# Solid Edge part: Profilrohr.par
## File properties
Username: bmolnar
Dokumentum tartalom típus: 0
Author: bmolnar
Last saved by: bmolnar
Revision: 97
Sűrűség: 0,000 kg/m^3
Pontosság: 0,990
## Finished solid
Body 1: solid body, 175 faces, 519 edges, 346 vertices.
  Faces by surface: cylinder 107, plane 68
  Edges by curve: line 305, circle 214
Bounding box of the edges (mm): 60.200 x 60.200 x 2844.000, from (-30.1, -30.1, -2784.5) to (30.1, 30.1, 59.5).
Cylindrical faces by radius (mm): R0.1 x16, R0.2 x30, R0.5 x28, R1 x8, R3.75 x8, R5 x4, R6 x4, R25 x1, R27 x8
Planar faces by outward normal: +x 6, +y 6, +z 1, -x 4, -y 4, -z 1, oblique 46
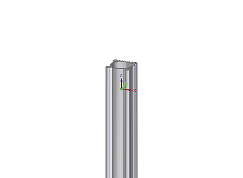
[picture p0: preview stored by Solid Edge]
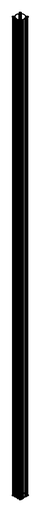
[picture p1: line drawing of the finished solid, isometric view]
